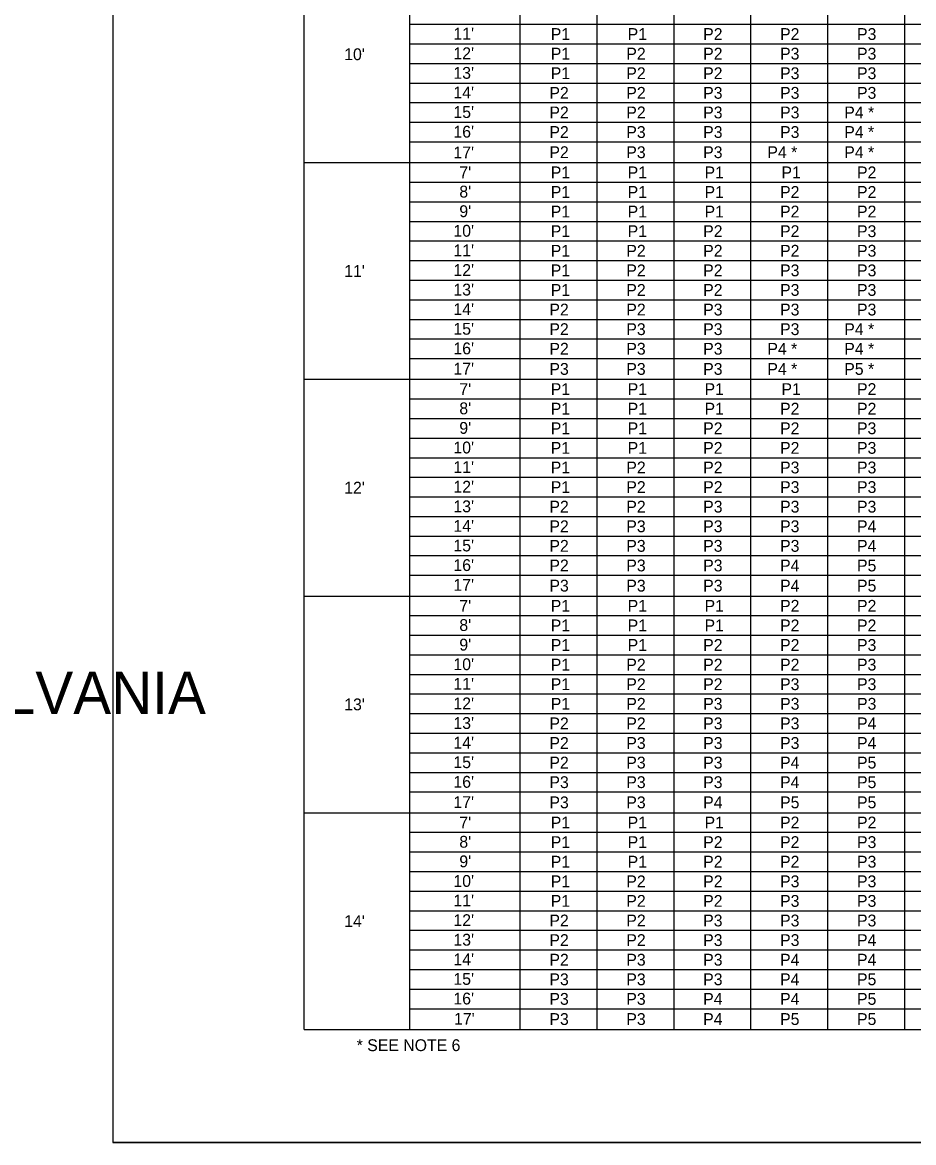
# Model space of a CAD drawing. Extents: x 637580 to 641008, y 294594 to 295782.
# Drawn here: x 638438.3 to 638664.4, y 295202.6 to 295486.9 of the extents above; entities that cross this region are included whole.
import ezdxf

# ---------------------------------------------------------------- set-up
doc = ezdxf.new("R2010")
doc.units = 0
doc.layers.add('1', color=7, linetype='Continuous')
doc.layers.add('2', color=7, linetype='Continuous')

msp = doc.modelspace()

# ---------------------------------------------------------------- linework, layer by layer
at = {"layer": '1'}
for p, q in [((638461.31, 295766.63), (638461.31, 295202.63)), ((638509.81, 295231.34), (638509.81, 295750.63)), ((638536.61, 295231.34), (638536.61, 295742.95)), ((638564.61, 295231.34), (638564.61, 295742.95)), ((638584.12, 295231.34), (638584.12, 295735.61)), ((638603.63, 295231.34), (638603.63, 295735.61)), ((638623.14, 295231.34), (638623.14, 295735.61)), ((638642.64, 295231.34), (638642.64, 295735.61)), ((638662.15, 295231.34), (638662.15, 295735.61)), ((638509.81, 295451.3), (638876.73, 295451.3)), ((638509.81, 295396.31), (638876.73, 295396.31)), ((638509.81, 295341.32), (638876.73, 295341.32)), ((638509.81, 295286.33), (638876.73, 295286.33)), ((638509.81, 295231.34), (638876.73, 295231.34)), ((639247.31, 295202.63), (638461.31, 295202.63)), ((638461.31, 295202.63), (639047.31, 295202.63))]:
    msp.add_line(p, q, dxfattribs=at)
at = {"layer": '2'}
for p, q in [((638536.61, 295486.4), (638876.73, 295486.4)), ((638536.61, 295481.43), (638876.73, 295481.43)), ((638536.61, 295476.45), (638876.73, 295476.45)), ((638536.61, 295471.48), (638876.73, 295471.48)), ((638536.61, 295466.51), (638876.73, 295466.51)), ((638536.61, 295461.54), (638876.73, 295461.54)), ((638536.61, 295456.56), (638876.73, 295456.56)), ((638536.61, 295446.33), (638876.73, 295446.33)), ((638536.61, 295441.35), (638876.73, 295441.35)), ((638536.61, 295436.38), (638876.73, 295436.38)), ((638536.61, 295431.41), (638876.73, 295431.41)), ((638536.61, 295426.44), (638876.73, 295426.44)), ((638536.61, 295421.46), (638876.73, 295421.46)), ((638536.61, 295416.49), (638876.73, 295416.49)), ((638536.61, 295411.52), (638876.73, 295411.52)), ((638536.61, 295406.55), (638876.73, 295406.55)), ((638536.61, 295401.57), (638876.73, 295401.57)), ((638536.61, 295391.34), (638876.73, 295391.34)), ((638536.61, 295386.36), (638876.73, 295386.36)), ((638536.61, 295381.39), (638876.73, 295381.39)), ((638536.61, 295376.42), (638876.73, 295376.42)), ((638536.61, 295371.45), (638876.73, 295371.45)), ((638536.61, 295366.47), (638876.73, 295366.47)), ((638536.61, 295361.5), (638876.73, 295361.5)), ((638536.61, 295356.53), (638876.73, 295356.53)), ((638536.61, 295351.56), (638876.73, 295351.56)), ((638536.61, 295346.58), (638876.73, 295346.58)), ((638536.61, 295336.35), (638876.73, 295336.35)), ((638536.61, 295331.37), (638876.73, 295331.37)), ((638536.61, 295326.4), (638876.73, 295326.4)), ((638536.61, 295321.43), (638876.73, 295321.43)), ((638536.61, 295316.46), (638876.73, 295316.46)), ((638536.61, 295311.48), (638876.73, 295311.48)), ((638536.61, 295306.51), (638876.73, 295306.51)), ((638536.61, 295301.54), (638876.73, 295301.54)), ((638536.61, 295296.57), (638876.73, 295296.57)), ((638536.61, 295291.59), (638876.73, 295291.59)), ((638536.61, 295281.36), (638876.73, 295281.36)), ((638536.61, 295276.38), (638876.73, 295276.38)), ((638536.61, 295271.41), (638876.73, 295271.41)), ((638536.61, 295266.44), (638876.73, 295266.44)), ((638536.61, 295261.47), (638876.73, 295261.47)), ((638536.61, 295256.49), (638876.73, 295256.49)), ((638536.61, 295251.52), (638876.73, 295251.52)), ((638536.61, 295246.55), (638876.73, 295246.55)), ((638536.61, 295241.58), (638876.73, 295241.58)), ((638536.61, 295236.6), (638876.73, 295236.6))]:
    msp.add_line(p, q, dxfattribs=at)

# ---------------------------------------------------------------- texts
at = {"layer": '1'}
for s, height, p in [("11'", 3, (638547.67, 295482.51)), ('P1', 3, (638572.36, 295482.41)), ('P1', 3, (638591.87, 295482.41)), ('P2', 3, (638611.03, 295482.41)), ('P2', 3, (638630.54, 295482.41)), ('P3', 3, (638650.05, 295482.41)), ("10'", 3, (638519.97, 295477.29)), ("12'", 3, (638547.67, 295477.53)), ('P1', 3, (638572.36, 295477.44)), ('P2', 3, (638591.53, 295477.44)), ('P2', 3, (638611.03, 295477.44)), ('P3', 3, (638630.54, 295477.44)), ('P3', 3, (638650.05, 295477.44)), ("13'", 3, (638547.67, 295472.56)), ('P1', 3, (638572.36, 295472.47)), ('P2', 3, (638591.53, 295472.47)), ('P2', 3, (638611.03, 295472.47)), ('P3', 3, (638630.54, 295472.47)), ('P3', 3, (638650.05, 295472.47)), ("14'", 3, (638547.67, 295467.59)), ('P2', 3, (638572.02, 295467.49)), ('P2', 3, (638591.53, 295467.49)), ('P3', 3, (638611.03, 295467.49)), ('P3', 3, (638630.54, 295467.49)), ('P3', 3, (638650.05, 295467.49)), ("15'", 3, (638547.67, 295462.62)), ('P2', 3, (638572.02, 295462.52)), ('P2', 3, (638591.53, 295462.52)), ('P3', 3, (638611.03, 295462.52)), ('P3', 3, (638630.54, 295462.52)), ('P4 *', 3, (638646.82, 295462.52)), ("16'", 3, (638547.67, 295457.64)), ('P2', 3, (638572.02, 295457.55)), ('P3', 3, (638591.53, 295457.55)), ('P3', 3, (638611.03, 295457.55)), ('P3', 3, (638630.54, 295457.55)), ('P4 *', 3, (638646.82, 295457.55)), ("17'", 3, (638547.67, 295452.37)), ('P2', 3, (638572.02, 295452.43)), ('P3', 3, (638591.53, 295452.43)), ('P3', 3, (638611.03, 295452.43)), ('P4 *', 3, (638627.31, 295452.43)), ('P4 *', 3, (638646.82, 295452.43)), ("7'", 3, (638549.17, 295447.31)), ('P1', 3, (638572.36, 295447.31)), ('P1', 3, (638591.87, 295447.31)), ('P1', 3, (638611.38, 295447.31)), ('P1', 3, (638630.88, 295447.31)), ('P2', 3, (638650.05, 295447.31)), ("8'", 3, (638549.17, 295442.43)), ('P1', 3, (638572.36, 295442.34)), ('P1', 3, (638591.87, 295442.34)), ('P1', 3, (638611.38, 295442.34)), ('P2', 3, (638630.54, 295442.34)), ('P2', 3, (638650.05, 295442.34)), ("9'", 3, (638549.17, 295437.46)), ('P1', 3, (638572.36, 295437.37)), ('P1', 3, (638591.87, 295437.37)), ('P1', 3, (638611.38, 295437.37)), ('P2', 3, (638630.54, 295437.37)), ('P2', 3, (638650.05, 295437.37)), ("10'", 3, (638547.67, 295432.49)), ('P1', 3, (638572.36, 295432.39)), ('P1', 3, (638591.87, 295432.39)), ('P2', 3, (638611.03, 295432.39)), ('P2', 3, (638630.54, 295432.39)), ('P3', 3, (638650.05, 295432.39)), ("11'", 3, (638547.67, 295427.52)), ('P1', 3, (638572.36, 295427.42)), ('P2', 3, (638591.53, 295427.42)), ('P2', 3, (638611.03, 295427.42)), ('P2', 3, (638630.54, 295427.42)), ('P3', 3, (638650.05, 295427.42)), ("12'", 3, (638547.67, 295422.54)), ("11'", 3, (638519.97, 295422.3)), ('P1', 3, (638572.36, 295422.45)), ('P2', 3, (638591.53, 295422.45)), ('P2', 3, (638611.03, 295422.45)), ('P3', 3, (638630.54, 295422.45)), ('P3', 3, (638650.05, 295422.45)), ("13'", 3, (638547.67, 295417.57)), ('P1', 3, (638572.36, 295417.48)), ('P2', 3, (638591.53, 295417.48)), ('P2', 3, (638611.03, 295417.48)), ('P3', 3, (638630.54, 295417.48)), ('P3', 3, (638650.05, 295417.48)), ("14'", 3, (638547.67, 295412.6)), ('P2', 3, (638572.02, 295412.5)), ('P2', 3, (638591.53, 295412.5)), ('P3', 3, (638611.03, 295412.5)), ('P3', 3, (638630.54, 295412.5)), ('P3', 3, (638650.05, 295412.5)), ("15'", 3, (638547.67, 295407.63)), ('P2', 3, (638572.02, 295407.53)), ('P3', 3, (638591.53, 295407.53)), ('P3', 3, (638611.03, 295407.53)), ('P3', 3, (638630.54, 295407.53)), ('P4 *', 3, (638646.82, 295407.53)), ("16'", 3, (638547.67, 295402.65)), ('P2', 3, (638572.02, 295402.56)), ('P3', 3, (638591.53, 295402.56)), ('P3', 3, (638611.03, 295402.56)), ('P4 *', 3, (638627.31, 295402.56)), ('P4 *', 3, (638646.82, 295402.56)), ("17'", 3, (638547.67, 295397.5)), ('P3', 3, (638572.02, 295397.44)), ('P3', 3, (638591.53, 295397.44)), ('P3', 3, (638611.03, 295397.44)), ('P4 *', 3, (638627.31, 295397.44)), ('P5 *', 3, (638646.82, 295397.44)), ("7'", 3, (638549.17, 295392.32)), ('P1', 3, (638572.36, 295392.32)), ('P1', 3, (638591.87, 295392.32)), ('P1', 3, (638611.38, 295392.32)), ('P1', 3, (638630.88, 295392.32)), ('P2', 3, (638650.05, 295392.32)), ("8'", 3, (638549.17, 295387.44)), ('P1', 3, (638572.36, 295387.35)), ('P1', 3, (638591.87, 295387.35)), ('P1', 3, (638611.38, 295387.35)), ('P2', 3, (638630.54, 295387.35)), ('P2', 3, (638650.05, 295387.35)), ("9'", 3, (638549.17, 295382.47)), ('P1', 3, (638572.36, 295382.38)), ('P1', 3, (638591.87, 295382.38)), ('P2', 3, (638611.03, 295382.38)), ('P2', 3, (638630.54, 295382.38)), ('P3', 3, (638650.05, 295382.38)), ("10'", 3, (638547.67, 295377.5)), ('P1', 3, (638572.36, 295377.4)), ('P1', 3, (638591.87, 295377.4)), ('P2', 3, (638611.03, 295377.4)), ('P2', 3, (638630.54, 295377.4)), ('P3', 3, (638650.05, 295377.4)), ("11'", 3, (638547.67, 295372.53)), ('P1', 3, (638572.36, 295372.43)), ('P2', 3, (638591.53, 295372.43)), ('P2', 3, (638611.03, 295372.43)), ('P3', 3, (638630.54, 295372.43)), ('P3', 3, (638650.05, 295372.43)), ("12'", 3, (638519.97, 295367.31)), ("12'", 3, (638547.67, 295367.55)), ('P1', 3, (638572.36, 295367.46)), ('P2', 3, (638591.53, 295367.46)), ('P2', 3, (638611.03, 295367.46)), ('P3', 3, (638630.54, 295367.46)), ('P3', 3, (638650.05, 295367.46)), ("13'", 3, (638547.67, 295362.58)), ('P2', 3, (638572.02, 295362.49)), ('P2', 3, (638591.53, 295362.49)), ('P3', 3, (638611.03, 295362.49)), ('P3', 3, (638630.54, 295362.49)), ('P3', 3, (638650.05, 295362.49)), ("14'", 3, (638547.67, 295357.61)), ('P2', 3, (638572.02, 295357.51)), ('P3', 3, (638591.53, 295357.51)), ('P3', 3, (638611.03, 295357.51)), ('P3', 3, (638630.54, 295357.51)), ('P4', 3, (638650.05, 295357.51)), ("15'", 3, (638547.67, 295352.64)), ('P2', 3, (638572.02, 295352.54)), ('P3', 3, (638591.53, 295352.54)), ('P3', 3, (638611.03, 295352.54)), ('P3', 3, (638630.54, 295352.54)), ('P4', 3, (638650.05, 295352.54)), ("16'", 3, (638547.67, 295347.66)), ('P2', 3, (638572.02, 295347.57)), ('P3', 3, (638591.53, 295347.57)), ('P3', 3, (638611.03, 295347.57)), ('P4', 3, (638630.54, 295347.57)), ('P5', 3, (638650.05, 295347.57)), ("17'", 3, (638547.67, 295342.64)), ('P3', 3, (638572.02, 295342.45)), ('P3', 3, (638591.53, 295342.45)), ('P3', 3, (638611.03, 295342.45)), ('P4', 3, (638630.54, 295342.45)), ('P5', 3, (638650.05, 295342.45)), ("7'", 3, (638549.17, 295337.33)), ('P1', 3, (638572.36, 295337.33)), ('P1', 3, (638591.87, 295337.33)), ('P1', 3, (638611.38, 295337.33)), ('P2', 3, (638630.54, 295337.33)), ('P2', 3, (638650.05, 295337.33)), ("8'", 3, (638549.17, 295332.45)), ('P1', 3, (638572.36, 295332.36)), ('P1', 3, (638591.87, 295332.36)), ('P1', 3, (638611.38, 295332.36)), ('P2', 3, (638630.54, 295332.36)), ('P2', 3, (638650.05, 295332.36)), ("9'", 3, (638549.17, 295327.48)), ('P1', 3, (638572.36, 295327.39)), ('P1', 3, (638591.87, 295327.39)), ('P2', 3, (638611.03, 295327.39)), ('P2', 3, (638630.54, 295327.39)), ('P3', 3, (638650.05, 295327.39)), ("10'", 3, (638547.67, 295322.51)), ('P1', 3, (638572.36, 295322.41)), ('P2', 3, (638591.53, 295322.41)), ('P2', 3, (638611.03, 295322.41)), ('P2', 3, (638630.54, 295322.41)), ('P3', 3, (638650.05, 295322.41)), ('COMMONWEALTH OF PENNSYLVANIA', 10.7828, (638218.9, 295311.36)), ("11'", 3, (638547.67, 295317.54)), ('P1', 3, (638572.36, 295317.44)), ('P2', 3, (638591.53, 295317.44)), ('P2', 3, (638611.03, 295317.44)), ('P3', 3, (638630.54, 295317.44)), ('P3', 3, (638650.05, 295317.44)), ("13'", 3, (638519.97, 295312.32)), ("12'", 3, (638547.67, 295312.56)), ('P1', 3, (638572.36, 295312.47)), ('P2', 3, (638591.53, 295312.47)), ('P3', 3, (638611.03, 295312.47)), ('P3', 3, (638630.54, 295312.47)), ('P3', 3, (638650.05, 295312.47)), ("13'", 3, (638547.67, 295307.59)), ('P2', 3, (638572.02, 295307.5)), ('P2', 3, (638591.53, 295307.5)), ('P3', 3, (638611.03, 295307.5)), ('P3', 3, (638630.54, 295307.5)), ('P4', 3, (638650.05, 295307.5)), ("14'", 3, (638547.67, 295302.62)), ('P2', 3, (638572.02, 295302.52)), ('P3', 3, (638591.53, 295302.52)), ('P3', 3, (638611.03, 295302.52)), ('P3', 3, (638630.54, 295302.52)), ('P4', 3, (638650.05, 295302.52)), ("15'", 3, (638547.67, 295297.65)), ('P2', 3, (638572.02, 295297.55)), ('P3', 3, (638591.53, 295297.55)), ('P3', 3, (638611.03, 295297.55)), ('P4', 3, (638630.54, 295297.55)), ('P5', 3, (638650.05, 295297.55)), ("16'", 3, (638547.67, 295292.67)), ('P3', 3, (638572.02, 295292.58)), ('P3', 3, (638591.53, 295292.58)), ('P3', 3, (638611.03, 295292.58)), ('P4', 3, (638630.54, 295292.58)), ('P5', 3, (638650.05, 295292.58)), ("17'", 3, (638547.67, 295287.52)), ('P3', 3, (638572.02, 295287.46)), ('P3', 3, (638591.53, 295287.46)), ('P4', 3, (638611.03, 295287.46)), ('P5', 3, (638630.54, 295287.46)), ('P5', 3, (638650.05, 295287.46)), ("7'", 3, (638549.17, 295282.34)), ('P1', 3, (638572.36, 295282.34)), ('P1', 3, (638591.87, 295282.34)), ('P1', 3, (638611.38, 295282.34)), ('P2', 3, (638630.54, 295282.34)), ('P2', 3, (638650.05, 295282.34)), ("8'", 3, (638549.17, 295277.46)), ('P1', 3, (638572.36, 295277.37)), ('P1', 3, (638591.87, 295277.37)), ('P2', 3, (638611.03, 295277.37)), ('P2', 3, (638630.54, 295277.37)), ('P3', 3, (638650.05, 295277.37)), ("9'", 3, (638549.17, 295272.49)), ('P1', 3, (638572.36, 295272.4)), ('P1', 3, (638591.87, 295272.4)), ('P2', 3, (638611.03, 295272.4)), ('P2', 3, (638630.54, 295272.4)), ('P3', 3, (638650.05, 295272.4)), ("10'", 3, (638547.67, 295267.52)), ('P1', 3, (638572.36, 295267.42)), ('P2', 3, (638591.53, 295267.42)), ('P2', 3, (638611.03, 295267.42)), ('P3', 3, (638630.54, 295267.42)), ('P3', 3, (638650.05, 295267.42)), ("11'", 3, (638547.67, 295262.55)), ('P1', 3, (638572.36, 295262.45)), ('P2', 3, (638591.53, 295262.45)), ('P2', 3, (638611.03, 295262.45)), ('P3', 3, (638630.54, 295262.45)), ('P3', 3, (638650.05, 295262.45)), ("14'", 3, (638519.97, 295257.33)), ("12'", 3, (638547.67, 295257.57)), ('P2', 3, (638572.02, 295257.48)), ('P2', 3, (638591.53, 295257.48)), ('P3', 3, (638611.03, 295257.48)), ('P3', 3, (638630.54, 295257.48)), ('P3', 3, (638650.05, 295257.48)), ("13'", 3, (638547.67, 295252.6)), ('P2', 3, (638572.02, 295252.51)), ('P2', 3, (638591.53, 295252.51)), ('P3', 3, (638611.03, 295252.51)), ('P3', 3, (638630.54, 295252.51)), ('P4', 3, (638650.05, 295252.51)), ("14'", 3, (638547.67, 295247.63)), ('P2', 3, (638572.02, 295247.53)), ('P3', 3, (638591.53, 295247.53)), ('P3', 3, (638611.03, 295247.53)), ('P4', 3, (638630.54, 295247.53)), ('P4', 3, (638650.05, 295247.53)), ("15'", 3, (638547.67, 295242.66)), ('P3', 3, (638572.02, 295242.56)), ('P3', 3, (638591.53, 295242.56)), ('P3', 3, (638611.03, 295242.56)), ('P4', 3, (638630.54, 295242.56)), ('P5', 3, (638650.05, 295242.56)), ("16'", 3, (638547.67, 295237.68)), ('P3', 3, (638572.02, 295237.59)), ('P3', 3, (638591.53, 295237.59)), ('P4', 3, (638611.03, 295237.59)), ('P4', 3, (638630.54, 295237.59)), ('P5', 3, (638650.05, 295237.59)), ("17'", 3, (638547.83, 295232.53)), ('P3', 3, (638572.02, 295232.47)), ('P3', 3, (638591.53, 295232.47)), ('P4', 3, (638611.03, 295232.47)), ('P5', 3, (638630.54, 295232.47)), ('P5', 3, (638650.05, 295232.47)), ('* SEE NOTE 6', 3, (638523.13, 295225.84))]:
    msp.add_text(s, height=height, dxfattribs=at).set_placement(p)

doc.saveas('drawing.dxf')
